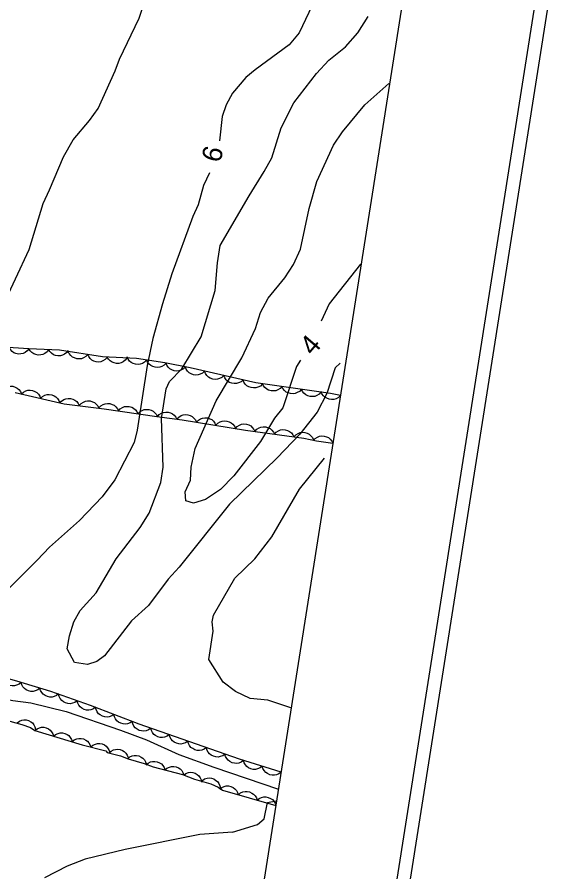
# Model space of a CAD drawing. Extents: x 282461 to 284471, y 5554090 to 5557646.
# Drawn here: x 283962.3 to 284046.6, y 5554641.4 to 5554771.5 of the extents above; entities that cross this region are included whole.
import ezdxf

# ---------------------------------------------------------------- set-up
doc = ezdxf.new("R2010")
doc.units = 0
for name, color, linetype in [('Niveau 1', 7, 'Continuous'), ('Niveau 2', 7, 'Continuous'), ('Niveau 22', 7, 'Continuous'), ('Niveau 44', 7, 'Continuous'), ('Niveau 60', 7, 'Continuous')]:
    doc.layers.add(name, color=color, linetype=linetype)

msp = doc.modelspace()

# ---------------------------------------------------------------- linework, layer by layer
at = {"layer": 'Niveau 1'}
for points in [[(284011.5, 5554718.88), (284010.71, 5554718.15), (284009.45, 5554714.26), (284007.96, 5554711.41), (284005.37, 5554708.03), (284001.9, 5554704.47), (283994.63, 5554697.37), (283987.01, 5554687.78), (283985.33, 5554685.99), (283982.31, 5554681.99), (283979.74, 5554679.65), (283975.64, 5554674.31), (283974.46, 5554673.46), (283973.03, 5554673), (283971.05, 5554673.29), (283969.96, 5554675.37), (283970.3, 5554677.37), (283970.96, 5554679.47), (283971.93, 5554681.22), (283974.39, 5554683.91), (283977.43, 5554689.06), (283981.06, 5554693.85), (283982.43, 5554696), (283984.19, 5554700.71), (283984.55, 5554703.05), (283984.32, 5554710.43), (283985.02, 5554714.97), (283985.53, 5554716.08), (283987.39, 5554717.99), (283990.34, 5554722.86), (283992.48, 5554729.9), (283992.8, 5554734.12), (283993.21, 5554736.79), (283997.62, 5554744.31), (283999.94, 5554748.05), (284001.08, 5554750.1), (284002.49, 5554754.68), (284004.44, 5554758.5), (284007.88, 5554762.94), (284009.74, 5554765.01), (284012.28, 5554767.02), (284014.17, 5554769.14), (284015.76, 5554771.65)], [(283995.09, 5554647.46), (283998.9, 5554648.62), (283999.9, 5554649.5), (284000.44, 5554651.96), (284001.73, 5554652.25)], [(283995.09, 5554647.46), (283990.12, 5554647.1), (283978.79, 5554644.81), (283972.67, 5554643.34), (283969.95, 5554642.26), (283966.53, 5554640.52)]]:
    msp.add_lwpolyline(points, dxfattribs=at)
at = {"layer": 'Niveau 2'}
for points in [[(283960, 5554727.21), (283964.15, 5554736.16), (283966.28, 5554743.17), (283967.26, 5554745.24), (283969.4, 5554750.25), (283970.87, 5554752.88), (283973.36, 5554755.79), (283974.68, 5554757.62), (283977.28, 5554763.37), (283977.9, 5554765.16), (283980.93, 5554771.4), (283983.24, 5554778.55)], [(284009.61, 5554778.4), (284005.26, 5554769.15), (284003.75, 5554767.32), (283998.53, 5554763.51), (283997.15, 5554762.35), (283995.09, 5554759.94), (283994.13, 5554758.2), (283993.51, 5554756.43), (283993.15, 5554752.7)], [(284005.43, 5554719.32), (284004.84, 5554718.36), (284002.75, 5554712.04), (284001.49, 5554710.51), (283999.36, 5554706.93), (283995.31, 5554701.73), (283993.27, 5554699.65), (283990.99, 5554698.12), (283989.18, 5554697.54), (283988.02, 5554697.89), (283987.9, 5554699.28), (283988.71, 5554701.04), (283988.83, 5554703.05), (283989.44, 5554705.88), (283992.63, 5554713.1), (283996.53, 5554719.67), (283998.61, 5554724.15), (283999.34, 5554726.58), (284000.52, 5554728.78), (284003.05, 5554731.85), (284004.4, 5554733.86), (284005.46, 5554736.24), (284006.75, 5554742.41), (284007.92, 5554746.5), (284010.46, 5554752.07), (284011.82, 5554754.09), (284015.21, 5554758.2), (284018.88, 5554761.46)], [(283991.62, 5554747.82), (283990.67, 5554745.91), (283989.88, 5554742.95), (283989.09, 5554741.2), (283985.86, 5554732.46), (283984.45, 5554727.87), (283982.98, 5554722.64), (283982.14, 5554718.49), (283980.62, 5554708.64), (283980.17, 5554706.8), (283977.21, 5554701.08), (283975.27, 5554698.49), (283971.84, 5554694.93), (283967.26, 5554690.85), (283965.4, 5554688.89), (283960.51, 5554684.02)], [(284014.56, 5554733.94), (284009.8, 5554727.89), (284008.57, 5554725.24)], [(284003.99, 5554666.41), (284000.48, 5554667.54), (283997.78, 5554667.81), (283995.55, 5554668.86), (283993.7, 5554670.31), (283991.49, 5554673.75), (283992.18, 5554678.08), (283992.03, 5554679.49), (283992.2, 5554680.48), (283995.46, 5554686.13), (283998.52, 5554689.08), (284001.07, 5554692.42), (284005.28, 5554699.67), (284009.09, 5554704.38)]]:
    msp.add_lwpolyline(points, dxfattribs=at)
at = {"layer": 'Niveau 22'}
msp.add_lwpolyline([(283885.8, 5554690.36), (283898.61, 5554686.93), (283911.65, 5554682.75), (283917.84, 5554680.93), (283923.74, 5554679), (283940.8, 5554673.72), (283956.57, 5554668.61), (283961.68, 5554667.5), (283964.44, 5554667.17), (283969.78, 5554665.84), (283978.09, 5554662.98), (283982.01, 5554661.51), (283986.94, 5554659.28), (283992.28, 5554657.36), (284002.09, 5554654.03)], dxfattribs=at)
at = {"layer": 'Niveau 44'}
for points in [[(284011.51, 5554713.92), (284010.01, 5554714.24), (283998.65, 5554715.89), (283988.66, 5554718.13), (283984.83, 5554718.9), (283980.52, 5554719.57), (283975.35, 5554719.81), (283968.77, 5554720.86), (283964.11, 5554721.05), (283956.18, 5554721.57)], [(283964.14, 5554721.05), (283963.88, 5554720.72), (283963.55, 5554720.48), (283963.26, 5554720.33), (283962.91, 5554720.26), (283962.54, 5554720.25), (283962.17, 5554720.34), (283961.86, 5554720.45), (283961.58, 5554720.66), (283961.33, 5554720.93), (283961.14, 5554721.24)], [(283967.13, 5554720.93), (283966.89, 5554720.59), (283966.56, 5554720.35), (283966.27, 5554720.19), (283965.93, 5554720.11), (283965.56, 5554720.09), (283965.18, 5554720.17), (283964.87, 5554720.27), (283964.59, 5554720.48), (283964.33, 5554720.74), (283964.14, 5554721.05)], [(283970.13, 5554720.8), (283969.88, 5554720.47), (283969.56, 5554720.23), (283969.27, 5554720.07), (283968.93, 5554719.99), (283968.56, 5554719.97), (283968.18, 5554720.05), (283967.87, 5554720.15), (283967.59, 5554720.36), (283967.32, 5554720.62), (283967.13, 5554720.93)], [(283973.08, 5554720.17), (283972.79, 5554719.87), (283972.44, 5554719.66), (283972.13, 5554719.54), (283971.78, 5554719.5), (283971.42, 5554719.53), (283971.05, 5554719.65), (283970.76, 5554719.79), (283970.5, 5554720.03), (283970.27, 5554720.32), (283970.12, 5554720.65)], [(283976.04, 5554719.7), (283975.75, 5554719.4), (283975.4, 5554719.19), (283975.1, 5554719.07), (283974.75, 5554719.03), (283974.38, 5554719.06), (283974.02, 5554719.18), (283973.72, 5554719.32), (283973.46, 5554719.55), (283973.23, 5554719.85), (283973.08, 5554720.17)], [(283979.04, 5554719.64), (283978.8, 5554719.3), (283978.47, 5554719.06), (283978.18, 5554718.9), (283977.83, 5554718.83), (283977.47, 5554718.81), (283977.09, 5554718.9), (283976.78, 5554719), (283976.5, 5554719.21), (283976.24, 5554719.47), (283976.05, 5554719.78)], [(283982.02, 5554719.34), (283981.74, 5554719.03), (283981.39, 5554718.83), (283981.08, 5554718.7), (283980.73, 5554718.66), (283980.37, 5554718.69), (283980, 5554718.81), (283979.71, 5554718.94), (283979.44, 5554719.18), (283979.21, 5554719.47), (283979.06, 5554719.8)], [(283984.99, 5554718.88), (283984.7, 5554718.57), (283984.35, 5554718.36), (283984.05, 5554718.24), (283983.7, 5554718.2), (283983.33, 5554718.23), (283982.97, 5554718.35), (283982.67, 5554718.48), (283982.41, 5554718.72), (283982.18, 5554719.01), (283982.02, 5554719.34)], [(283987.93, 5554718.28), (283987.63, 5554717.98), (283987.27, 5554717.8), (283986.96, 5554717.68), (283986.61, 5554717.66), (283986.24, 5554717.7), (283985.88, 5554717.84), (283985.59, 5554717.99), (283985.34, 5554718.24), (283985.13, 5554718.54), (283984.99, 5554718.87)], [(283990.86, 5554717.64), (283990.55, 5554717.35), (283990.19, 5554717.17), (283989.88, 5554717.06), (283989.53, 5554717.05), (283989.16, 5554717.1), (283988.81, 5554717.24), (283988.52, 5554717.4), (283988.27, 5554717.65), (283988.06, 5554717.96), (283987.93, 5554718.29)], [(283993.79, 5554716.98), (283993.48, 5554716.69), (283993.12, 5554716.51), (283992.8, 5554716.41), (283992.45, 5554716.39), (283992.09, 5554716.44), (283991.73, 5554716.59), (283991.45, 5554716.74), (283991.2, 5554717), (283990.99, 5554717.3), (283990.86, 5554717.64)], [(283996.71, 5554716.32), (283996.41, 5554716.04), (283996.04, 5554715.86), (283995.73, 5554715.75), (283995.38, 5554715.74), (283995.01, 5554715.79), (283994.66, 5554715.93), (283994.37, 5554716.09), (283994.13, 5554716.34), (283993.92, 5554716.65), (283993.79, 5554716.98)], [(283999.64, 5554715.67), (283999.34, 5554715.38), (283998.97, 5554715.2), (283998.66, 5554715.09), (283998.31, 5554715.08), (283997.94, 5554715.13), (283997.59, 5554715.28), (283997.3, 5554715.43), (283997.05, 5554715.68), (283996.84, 5554715.99), (283996.71, 5554716.32)], [(283960.04, 5554714.71), (283960.32, 5554715.01), (283960.68, 5554715.21), (283960.98, 5554715.33), (283961.33, 5554715.37), (283961.7, 5554715.34), (283962.06, 5554715.21), (283962.36, 5554715.07), (283962.62, 5554714.83), (283962.84, 5554714.54), (283962.99, 5554714.21)], [(284002.62, 5554715.31), (284002.34, 5554715), (284001.99, 5554714.8), (284001.69, 5554714.67), (284001.34, 5554714.63), (284000.97, 5554714.65), (284000.6, 5554714.77), (284000.31, 5554714.9), (284000.04, 5554715.13), (283999.81, 5554715.42), (283999.65, 5554715.74)], [(284005.59, 5554714.88), (284005.31, 5554714.57), (284004.96, 5554714.37), (284004.66, 5554714.24), (284004.31, 5554714.2), (284003.94, 5554714.22), (284003.57, 5554714.33), (284003.28, 5554714.47), (284003.01, 5554714.7), (284002.78, 5554714.99), (284002.62, 5554715.31)], [(284008.56, 5554714.45), (284008.28, 5554714.14), (284007.93, 5554713.93), (284007.62, 5554713.8), (284007.28, 5554713.76), (284006.91, 5554713.79), (284006.54, 5554713.9), (284006.24, 5554714.04), (284005.98, 5554714.27), (284005.75, 5554714.56), (284005.59, 5554714.88)], [(283962.05, 5554714.37), (283969.52, 5554712.69), (283975.59, 5554711.93), (283983.57, 5554710.72), (283987.46, 5554710.23), (283997.09, 5554708.68), (284005.96, 5554707.42), (284007.9, 5554707.02), (284010.37, 5554706.69)], [(283962.98, 5554714.16), (283963.29, 5554714.45), (283963.65, 5554714.63), (283963.97, 5554714.73), (283964.32, 5554714.75), (283964.68, 5554714.7), (283965.04, 5554714.55), (283965.32, 5554714.4), (283965.57, 5554714.14), (283965.78, 5554713.84), (283965.91, 5554713.5)], [(283965.91, 5554713.5), (283966.21, 5554713.79), (283966.58, 5554713.97), (283966.89, 5554714.07), (283967.24, 5554714.09), (283967.61, 5554714.04), (283967.96, 5554713.89), (283968.25, 5554713.74), (283968.5, 5554713.48), (283968.71, 5554713.18), (283968.84, 5554712.84)], [(284011.51, 5554713.92), (284011.21, 5554713.63), (284010.85, 5554713.45), (284010.53, 5554713.34), (284010.18, 5554713.32), (284009.82, 5554713.37), (284009.46, 5554713.51), (284009.17, 5554713.66), (284008.93, 5554713.91), (284008.71, 5554714.21), (284008.58, 5554714.55)], [(283968.83, 5554712.78), (283969.1, 5554713.09), (283969.45, 5554713.31), (283969.75, 5554713.44), (283970.1, 5554713.49), (283970.46, 5554713.47), (283970.83, 5554713.36), (283971.13, 5554713.24), (283971.4, 5554713.01), (283971.64, 5554712.73), (283971.8, 5554712.4)], [(283971.8, 5554712.4), (283972.08, 5554712.72), (283972.42, 5554712.93), (283972.72, 5554713.07), (283973.07, 5554713.12), (283973.44, 5554713.1), (283973.81, 5554712.99), (283974.11, 5554712.87), (283974.38, 5554712.64), (283974.61, 5554712.35), (283974.78, 5554712.03)], [(283974.78, 5554712.05), (283975.06, 5554712.36), (283975.42, 5554712.57), (283975.72, 5554712.69), (283976.07, 5554712.73), (283976.44, 5554712.71), (283976.8, 5554712.59), (283977.1, 5554712.45), (283977.36, 5554712.22), (283977.59, 5554711.93), (283977.75, 5554711.6)], [(283977.75, 5554711.6), (283978.03, 5554711.91), (283978.38, 5554712.12), (283978.69, 5554712.24), (283979.04, 5554712.28), (283979.4, 5554712.26), (283979.77, 5554712.14), (283980.06, 5554712), (283980.33, 5554711.77), (283980.56, 5554711.48), (283980.71, 5554711.15)], [(283980.71, 5554711.15), (283981, 5554711.46), (283981.35, 5554711.67), (283981.65, 5554711.79), (283982, 5554711.83), (283982.37, 5554711.81), (283982.73, 5554711.69), (283983.03, 5554711.55), (283983.29, 5554711.32), (283983.52, 5554711.03), (283983.68, 5554710.7)], [(283983.68, 5554710.71), (283983.95, 5554711.02), (283984.3, 5554711.23), (283984.6, 5554711.37), (283984.95, 5554711.42), (283985.32, 5554711.4), (283985.69, 5554711.29), (283985.99, 5554711.17), (283986.25, 5554710.94), (283986.49, 5554710.65), (283986.65, 5554710.33)], [(283986.66, 5554710.36), (283986.94, 5554710.66), (283987.3, 5554710.87), (283987.6, 5554710.99), (283987.95, 5554711.03), (283988.32, 5554711), (283988.68, 5554710.88), (283988.98, 5554710.74), (283989.24, 5554710.5), (283989.47, 5554710.21), (283989.62, 5554709.88)], [(283989.62, 5554709.88), (283989.91, 5554710.19), (283990.26, 5554710.39), (283990.56, 5554710.51), (283990.91, 5554710.55), (283991.28, 5554710.52), (283991.65, 5554710.4), (283991.94, 5554710.26), (283992.2, 5554710.02), (283992.43, 5554709.73), (283992.58, 5554709.41)], [(283992.58, 5554709.41), (283992.87, 5554709.71), (283993.22, 5554709.91), (283993.53, 5554710.04), (283993.88, 5554710.07), (283994.24, 5554710.05), (283994.61, 5554709.92), (283994.9, 5554709.79), (283995.16, 5554709.55), (283995.39, 5554709.26), (283995.54, 5554708.93)], [(283995.54, 5554708.93), (283995.83, 5554709.23), (283996.18, 5554709.44), (283996.49, 5554709.56), (283996.84, 5554709.6), (283997.21, 5554709.57), (283997.57, 5554709.45), (283997.87, 5554709.31), (283998.12, 5554709.07), (283998.35, 5554708.78), (283998.5, 5554708.45)], [(283998.51, 5554708.48), (283998.79, 5554708.79), (283999.14, 5554709), (283999.44, 5554709.13), (283999.79, 5554709.17), (284000.16, 5554709.15), (284000.52, 5554709.03), (284000.82, 5554708.9), (284001.09, 5554708.67), (284001.32, 5554708.38), (284001.48, 5554708.06)], [(284001.48, 5554708.06), (284001.76, 5554708.37), (284002.11, 5554708.58), (284002.41, 5554708.71), (284002.76, 5554708.75), (284003.13, 5554708.73), (284003.49, 5554708.61), (284003.79, 5554708.48), (284004.06, 5554708.25), (284004.29, 5554707.96), (284004.45, 5554707.63)], [(284004.45, 5554707.63), (284004.73, 5554707.94), (284005.08, 5554708.15), (284005.38, 5554708.28), (284005.73, 5554708.33), (284006.1, 5554708.31), (284006.46, 5554708.19), (284006.76, 5554708.06), (284007.03, 5554707.82), (284007.26, 5554707.54), (284007.42, 5554707.21)], [(284007.4, 5554707.09), (284007.67, 5554707.4), (284008.02, 5554707.61), (284008.32, 5554707.74), (284008.67, 5554707.79), (284009.04, 5554707.77), (284009.41, 5554707.66), (284009.71, 5554707.53), (284009.97, 5554707.3), (284010.21, 5554707.01), (284010.37, 5554706.69)], [(284002.49, 5554656.61), (283996.18, 5554658.57), (283980.92, 5554663.91), (283973.51, 5554666.75), (283967.45, 5554668.88), (283962.29, 5554670.44), (283945.43, 5554675.16), (283936.89, 5554677.23), (283920.05, 5554682.94), (283912.42, 5554685.33), (283894.1, 5554690.59)], [(283962.94, 5554670.26), (283962.63, 5554669.99), (283962.25, 5554669.83), (283961.94, 5554669.74), (283961.59, 5554669.74), (283961.23, 5554669.81), (283960.88, 5554669.97), (283960.6, 5554670.14), (283960.37, 5554670.41), (283960.18, 5554670.72), (283960.07, 5554671.06)], [(283965.8, 5554669.38), (283965.48, 5554669.12), (283965.1, 5554668.96), (283964.78, 5554668.88), (283964.43, 5554668.89), (283964.07, 5554668.97), (283963.73, 5554669.14), (283963.46, 5554669.31), (283963.23, 5554669.58), (283963.05, 5554669.9), (283962.94, 5554670.24)], [(283968.66, 5554668.51), (283968.34, 5554668.25), (283967.96, 5554668.1), (283967.65, 5554668.02), (283967.3, 5554668.03), (283966.94, 5554668.1), (283966.59, 5554668.27), (283966.32, 5554668.45), (283966.09, 5554668.72), (283965.91, 5554669.04), (283965.8, 5554669.38)], [(283971.46, 5554667.47), (283971.13, 5554667.22), (283970.75, 5554667.08), (283970.43, 5554667.02), (283970.08, 5554667.04), (283969.72, 5554667.14), (283969.39, 5554667.32), (283969.12, 5554667.51), (283968.91, 5554667.79), (283968.74, 5554668.11), (283968.64, 5554668.46)], [(283974.28, 5554666.48), (283973.95, 5554666.23), (283973.57, 5554666.09), (283973.25, 5554666.03), (283972.9, 5554666.05), (283972.54, 5554666.14), (283972.21, 5554666.33), (283971.94, 5554666.52), (283971.73, 5554666.8), (283971.56, 5554667.12), (283971.46, 5554667.47)], [(283977.07, 5554665.39), (283976.73, 5554665.15), (283976.34, 5554665.02), (283976.02, 5554664.96), (283975.67, 5554665), (283975.32, 5554665.1), (283974.99, 5554665.3), (283974.73, 5554665.49), (283974.52, 5554665.78), (283974.36, 5554666.11), (283974.28, 5554666.46)], [(283960.34, 5554664.6), (283963.04, 5554663.87), (283964.39, 5554663.4), (283965.06, 5554662.94), (283972.24, 5554660.78), (283975.84, 5554659.82), (283976.06, 5554659.59), (283978.09, 5554659.1), (283979.21, 5554658.63), (283981.68, 5554657.91), (283983.03, 5554657.43), (283987.52, 5554656.23), (283989.31, 5554655.52), (283991.79, 5554654.8), (283992.91, 5554654.33), (283993.58, 5554653.87), (284001.69, 5554651.51)], [(283962.35, 5554664.11), (283962.68, 5554664.36), (283963.06, 5554664.49), (283963.37, 5554664.56), (283963.72, 5554664.54), (283964.07, 5554664.45), (283964.41, 5554664.26), (283964.67, 5554664.08), (283964.88, 5554663.8), (283965.05, 5554663.48), (283965.14, 5554663.14)], [(283979.86, 5554664.32), (283979.52, 5554664.08), (283979.13, 5554663.95), (283978.81, 5554663.89), (283978.46, 5554663.93), (283978.11, 5554664.03), (283977.78, 5554664.23), (283977.52, 5554664.42), (283977.31, 5554664.71), (283977.15, 5554665.04), (283977.07, 5554665.39)], [(283982.67, 5554663.3), (283982.33, 5554663.05), (283981.95, 5554662.91), (283981.63, 5554662.84), (283981.28, 5554662.87), (283980.93, 5554662.96), (283980.59, 5554663.15), (283980.32, 5554663.33), (283980.11, 5554663.61), (283979.94, 5554663.94), (283979.85, 5554664.29)], [(283965.05, 5554662.94), (283965.37, 5554663.2), (283965.74, 5554663.36), (283966.05, 5554663.44), (283966.4, 5554663.43), (283966.76, 5554663.35), (283967.1, 5554663.19), (283967.37, 5554663.01), (283967.59, 5554662.75), (283967.78, 5554662.43), (283967.88, 5554662.09)], [(283985.49, 5554662.31), (283985.16, 5554662.06), (283984.77, 5554661.93), (283984.45, 5554661.86), (283984.1, 5554661.88), (283983.75, 5554661.98), (283983.41, 5554662.16), (283983.15, 5554662.35), (283982.93, 5554662.63), (283982.76, 5554662.95), (283982.67, 5554663.3)], [(283967.88, 5554662.09), (283968.2, 5554662.35), (283968.57, 5554662.5), (283968.89, 5554662.59), (283969.24, 5554662.57), (283969.59, 5554662.5), (283969.93, 5554662.33), (283970.2, 5554662.16), (283970.43, 5554661.89), (283970.61, 5554661.58), (283970.72, 5554661.24)], [(283970.72, 5554661.24), (283971.04, 5554661.5), (283971.41, 5554661.65), (283971.72, 5554661.73), (283972.07, 5554661.72), (283972.43, 5554661.65), (283972.77, 5554661.48), (283973.04, 5554661.31), (283973.26, 5554661.04), (283973.45, 5554660.72), (283973.55, 5554660.38)], [(283988.31, 5554661.32), (283987.98, 5554661.08), (283987.6, 5554660.94), (283987.27, 5554660.87), (283986.92, 5554660.9), (283986.57, 5554660.99), (283986.23, 5554661.17), (283985.97, 5554661.36), (283985.75, 5554661.64), (283985.58, 5554661.96), (283985.49, 5554662.31)], [(283973.57, 5554660.43), (283973.88, 5554660.7), (283974.24, 5554660.86), (283974.56, 5554660.95), (283974.9, 5554660.95), (283975.26, 5554660.89), (283975.61, 5554660.73), (283975.88, 5554660.57), (283976.11, 5554660.31), (283976.31, 5554660), (283976.43, 5554659.66)], [(283991.13, 5554660.34), (283990.8, 5554660.09), (283990.42, 5554659.95), (283990.09, 5554659.88), (283989.75, 5554659.91), (283989.39, 5554660), (283989.05, 5554660.19), (283988.79, 5554660.37), (283988.58, 5554660.65), (283988.4, 5554660.98), (283988.31, 5554661.32)], [(283993.95, 5554659.35), (283993.62, 5554659.1), (283993.24, 5554658.96), (283992.92, 5554658.9), (283992.57, 5554658.92), (283992.21, 5554659.01), (283991.88, 5554659.2), (283991.61, 5554659.38), (283991.4, 5554659.66), (283991.22, 5554659.99), (283991.13, 5554660.34)], [(283976.34, 5554659.52), (283976.65, 5554659.8), (283977.01, 5554659.97), (283977.32, 5554660.07), (283977.66, 5554660.08), (283978.03, 5554660.03), (283978.37, 5554659.88), (283978.65, 5554659.72), (283978.89, 5554659.47), (283979.09, 5554659.16), (283979.22, 5554658.83)], [(283979.16, 5554658.64), (283979.48, 5554658.91), (283979.85, 5554659.06), (283980.16, 5554659.15), (283980.51, 5554659.14), (283980.87, 5554659.07), (283981.21, 5554658.9), (283981.48, 5554658.73), (283981.7, 5554658.47), (283981.89, 5554658.15), (283982, 5554657.82)], [(283996.77, 5554658.36), (283996.44, 5554658.11), (283996.06, 5554657.98), (283995.74, 5554657.91), (283995.39, 5554657.94), (283995.03, 5554658.03), (283994.7, 5554658.21), (283994.43, 5554658.4), (283994.22, 5554658.68), (283994.04, 5554659), (283993.95, 5554659.35)], [(283981.97, 5554657.71), (283982.28, 5554657.98), (283982.65, 5554658.15), (283982.96, 5554658.24), (283983.31, 5554658.24), (283983.67, 5554658.18), (283984.01, 5554658.02), (283984.29, 5554657.85), (283984.52, 5554657.59), (283984.71, 5554657.28), (283984.83, 5554656.95)], [(283999.64, 5554657.5), (283999.31, 5554657.24), (283998.93, 5554657.09), (283998.62, 5554657.01), (283998.27, 5554657.02), (283997.91, 5554657.1), (283997.56, 5554657.27), (283997.29, 5554657.45), (283997.07, 5554657.72), (283996.89, 5554658.04), (283996.78, 5554658.38)], [(283984.83, 5554656.95), (283985.14, 5554657.22), (283985.51, 5554657.38), (283985.82, 5554657.47), (283986.17, 5554657.47), (283986.53, 5554657.41), (283986.87, 5554657.25), (283987.15, 5554657.09), (283987.38, 5554656.83), (283987.57, 5554656.52), (283987.69, 5554656.18)], [(283987.68, 5554656.16), (283988.02, 5554656.4), (283988.41, 5554656.52), (283988.73, 5554656.57), (283989.07, 5554656.53), (283989.42, 5554656.43), (283989.75, 5554656.23), (283990, 5554656.04), (283990.2, 5554655.75), (283990.36, 5554655.42), (283990.44, 5554655.07)], [(284002.49, 5554656.61), (284002.17, 5554656.35), (284001.79, 5554656.2), (284001.47, 5554656.12), (284001.12, 5554656.13), (284000.76, 5554656.21), (284000.42, 5554656.39), (284000.15, 5554656.56), (283999.92, 5554656.83), (283999.74, 5554657.15), (283999.64, 5554657.5)], [(283990.53, 5554655.33), (283990.87, 5554655.56), (283991.26, 5554655.67), (283991.58, 5554655.72), (283991.92, 5554655.67), (283992.27, 5554655.56), (283992.59, 5554655.35), (283992.84, 5554655.15), (283993.04, 5554654.87), (283993.19, 5554654.53), (283993.26, 5554654.18)], [(283993.16, 5554653.99), (283993.48, 5554654.26), (283993.85, 5554654.41), (283994.16, 5554654.5), (283994.51, 5554654.49), (283994.87, 5554654.42), (283995.21, 5554654.25), (283995.48, 5554654.08), (283995.71, 5554653.82), (283995.89, 5554653.5), (283996, 5554653.16)], [(283996, 5554653.16), (283996.32, 5554653.43), (283996.69, 5554653.58), (283997.01, 5554653.67), (283997.35, 5554653.66), (283997.71, 5554653.59), (283998.05, 5554653.42), (283998.32, 5554653.25), (283998.55, 5554652.99), (283998.74, 5554652.68), (283998.85, 5554652.34)], [(283998.85, 5554652.34), (283999.16, 5554652.6), (283999.53, 5554652.76), (283999.85, 5554652.84), (284000.2, 5554652.83), (284000.55, 5554652.76), (284000.89, 5554652.6), (284001.17, 5554652.43), (284001.39, 5554652.16), (284001.58, 5554651.85), (284001.69, 5554651.51)]]:
    msp.add_lwpolyline(points, dxfattribs=at)
at = {"layer": 'Niveau 60'}
for points in [[(283935.57, 5554089.71), (284458.46, 5557413.53), (282983.71, 5557645.53), (282460.81, 5554321.72), (283935.57, 5554089.71)], [(283933.91, 5554092), (284456.17, 5557411.87), (282985.38, 5557643.25), (282463.1, 5554323.39), (283933.91, 5554092)], [(282485.97, 5554340.04), (282921.22, 5557106.72), (284352.51, 5556881.56), (283917.27, 5554114.87), (282485.97, 5554340.04)]]:
    msp.add_lwpolyline(points, dxfattribs=at)

# ---------------------------------------------------------------- texts
at = {"layer": 'Niveau 2'}
for s, rotation, p in [('6', 73.9834, (283993.18, 5554749.23)), ('4', 49.514, (284007.34, 5554719.84))]:
    msp.add_text(s, height=3, rotation=rotation, dxfattribs=at).set_placement(p)

doc.saveas('drawing.dxf')
